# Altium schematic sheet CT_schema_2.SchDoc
size 255 x 159 mm
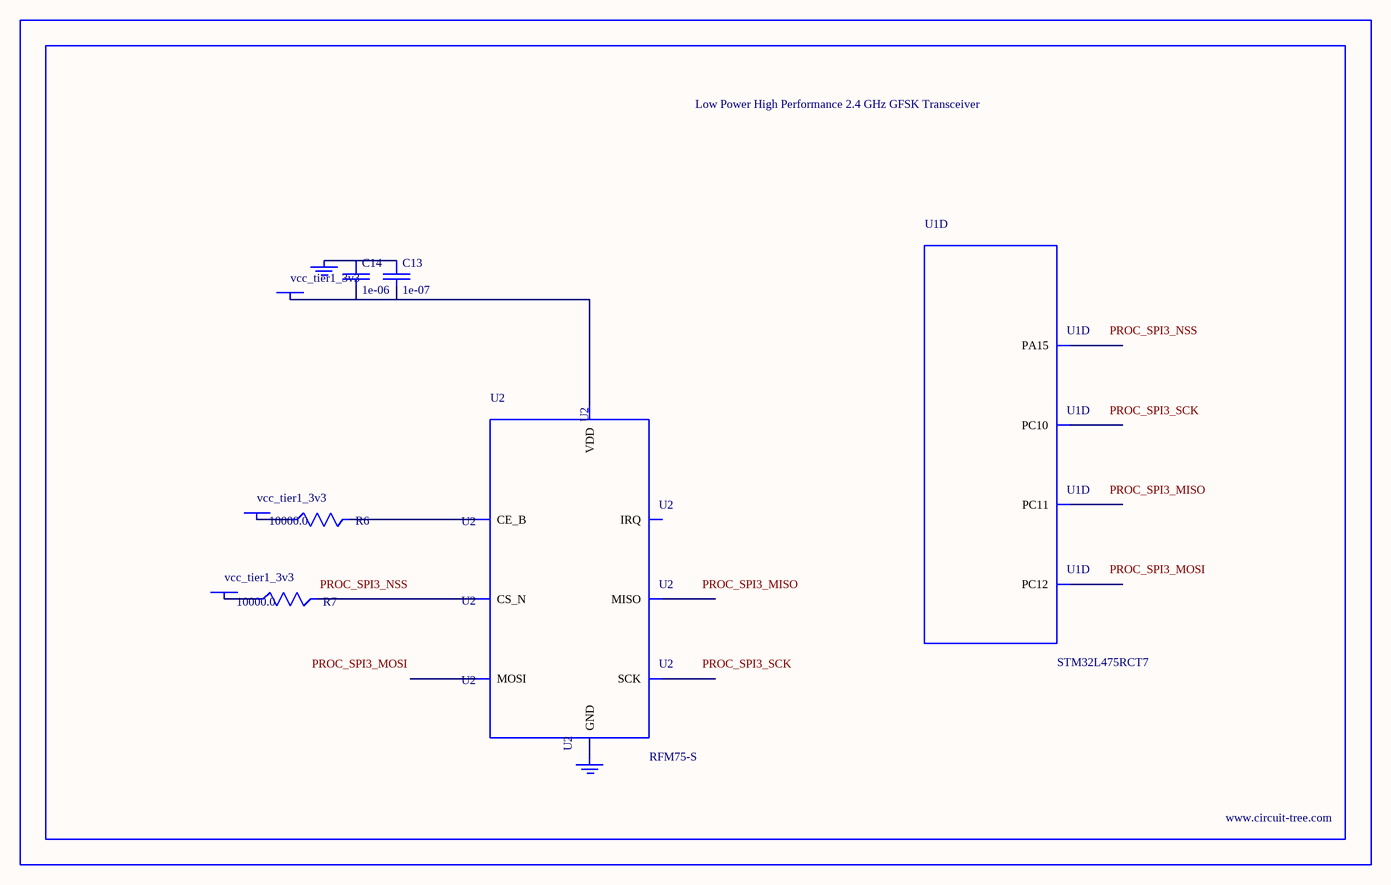
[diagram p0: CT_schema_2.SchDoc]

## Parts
BORDER1  (no value)
C13  1e-07  [C0402]
C14  1e-06  [C0603]
GND_INSTANCE_1_0  (no value)
GND_INSTANCE_1_1  (no value)
POWER_INSTANCE_1_0  vcc_tier1_3v3
POWER_INSTANCE_1_1  vcc_tier1_3v3
POWER_INSTANCE_1_2  vcc_tier1_3v3
R6  10000.0  [R0603]
R7  10000.0  [R0603]
U1  STM32L475RCT7  [LQFP64]  (part D of 8)
U2  RFM75-S  [RFM75-S]

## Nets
NetC13_1: C13.1 C14.1 GND_INSTANCE_1_0.0(GND)
NetC13_2: C13.2 C14.2 POWER_INSTANCE_1_0.0(PWR) U2.2(VDD)
NetGND_INSTANCE_1_1_0: GND_INSTANCE_1_1.0(GND) U2.1(GND)
NetPOWER_INSTANCE_1_1_0: POWER_INSTANCE_1_1.0(PWR) R6.1
NetPOWER_INSTANCE_1_2_0: POWER_INSTANCE_1_2.0(PWR) R7.1
NetR6_2: R6.2 U2.3(CE_B)
NetR7_2: R7.2 U2.4(CS_N)

Not connected (* = marked no-connect by the designer): U1 50(PA15) 51(PC10) 52(PC11) 53(PC12); U2 5(SCK) 6(MOSI) 7(MISO) 8(IRQ)

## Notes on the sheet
- Labels drawn without touching a wire or pin: PROC_SPI3_MISO, PROC_SPI3_MOSI, PROC_SPI3_NSS, PROC_SPI3_SCK

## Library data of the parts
BORDER1 = BORDER_PAGE1
C13 = C0402C104K3RACTU
C14 = C0603C105K3RACTU
GND_INSTANCE_1_0 GND_INSTANCE_1_1 = GND
POWER_INSTANCE_1_0-POWER_INSTANCE_1_2 = PWR
R6 R7 = RC0603JR-0710KL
